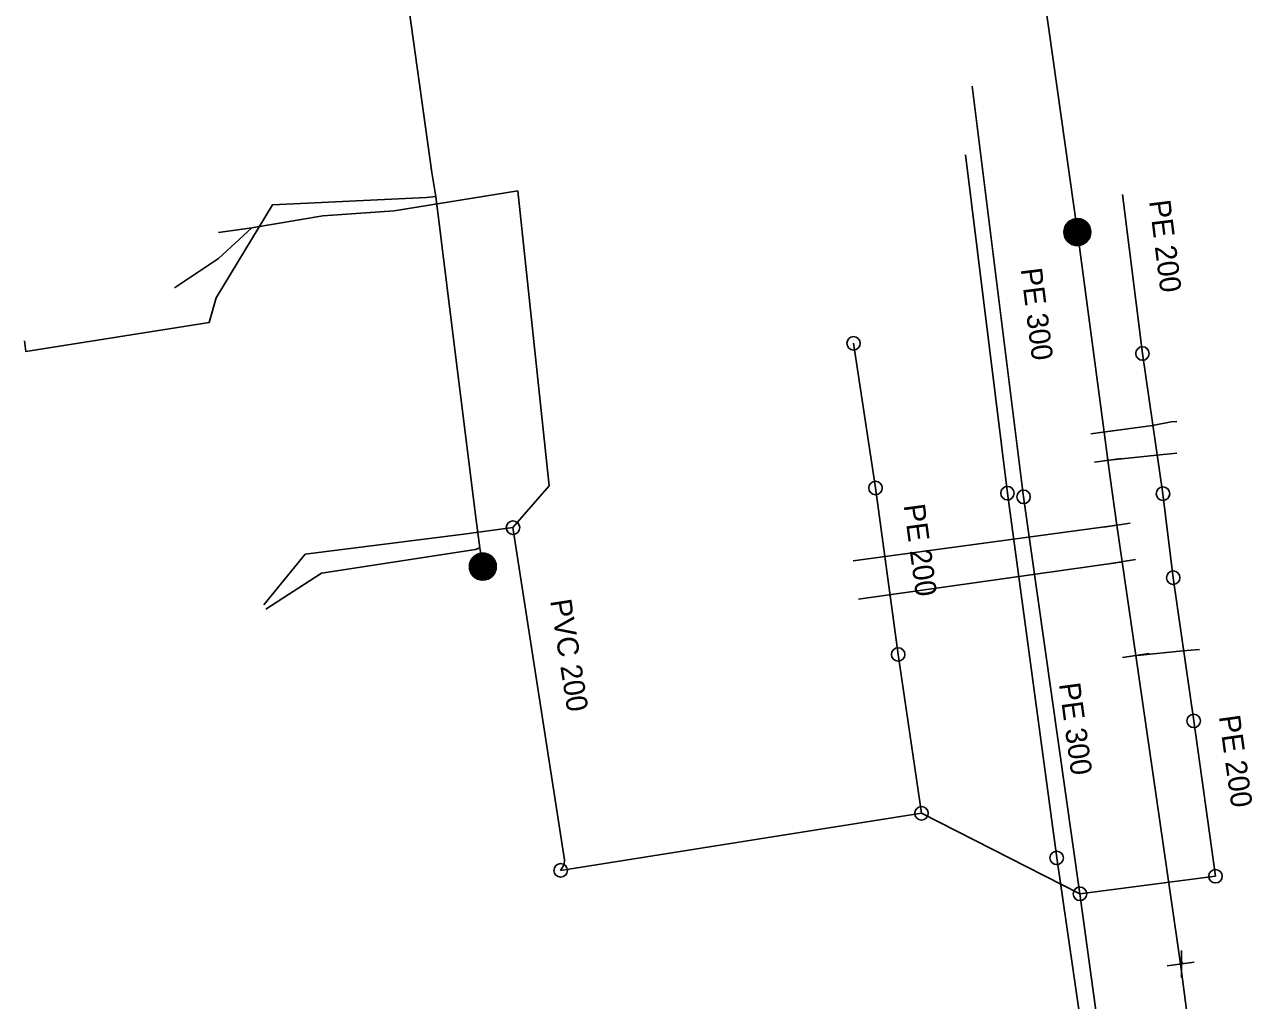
# Model space of a CAD drawing. Extents: x -867696 to -865033, y -1042522 to -1039817.
# Drawn here: x -866756.7 to -866641, y -1040051.9 to -1039959.9 of the extents above; entities that cross this region are included whole.
import ezdxf

# ---------------------------------------------------------------- set-up
doc = ezdxf.new("R2010")
doc.units = 0
for name, color, linetype in [('KN - destova', 7, 'Continuous'), ('KN - jednotna', 7, 'Continuous'), ('KN - popis material', 7, 'Continuous'), ('KN - pripojka', 7, 'Continuous'), ('KN - sachta komora', 7, 'Continuous'), ('KN - splaskova', 7, 'Continuous'), ('Level 1', 7, 'Continuous'), ('V - armatura', 7, 'Continuous'), ('V - hydrant', 7, 'Continuous'), ('V - ostatni', 7, 'Continuous'), ('V - pripojka', 7, 'Continuous'), ('V - rozvadeci', 7, 'Continuous')]:
    doc.layers.add(name, color=color, linetype=linetype)

# ---------------------------------------------------------------- blocks, each defined once
blk = doc.blocks.new('100.M')
at = {"layer": 'Level 1'}
blk.add_circle((0, 0), 1.27, dxfattribs=at)
blk = doc.blocks.new('160')
at = {"layer": 'Level 1'}
for p, q in [((-1.26, -0.04), (0.05, 1.27)), ((-1.26, -0.06), (0.06, 1.27)), ((-1.26, -0.07), (0.08, 1.27)), ((-1.26, -0.09), (0.09, 1.27)), ((-1.26, 0.11), (-0.12, 1.26)), ((-1.26, 0.1), (-0.1, 1.26)), ((-1.26, 0.08), (-0.09, 1.26)), ((-1.26, 0.07), (-0.07, 1.26)), ((-1.26, 0.06), (-0.06, 1.26)), ((-1.26, 0.04), (-0.04, 1.26)), ((-1.26, 0.03), (-0.03, 1.26)), ((-1.26, 0.01), (-0.01, 1.26)), ((-1.26, 0), (0, 1.26)), ((-1.26, -0.02), (0.02, 1.26)), ((-1.26, -0.03), (0.03, 1.26)), ((-1.26, -0.1), (0.1, 1.26)), ((-1.26, -0.11), (0.12, 1.26)), ((-1.26, -0.13), (0.13, 1.26)), ((-1.26, -0.14), (0.14, 1.26)), ((-1.26, 0.17), (-0.18, 1.25)), ((-1.26, 0.15), (-0.16, 1.25)), ((-1.26, 0.14), (-0.15, 1.25)), ((-1.26, 0.13), (-0.13, 1.25)), ((-1.26, -0.16), (0.15, 1.25)), ((-1.26, -0.17), (0.16, 1.25)), ((-1.25, 0.21), (-0.21, 1.25)), ((-1.25, 0.19), (-0.19, 1.25)), ((-1.25, -0.18), (0.17, 1.25)), ((-1.25, -0.19), (0.19, 1.25)), ((-1.25, -0.2), (0.2, 1.24)), ((-1.25, -0.21), (0.21, 1.24)), ((-1.24, 0.25), (-0.24, 1.25)), ((-1.24, 0.23), (-0.22, 1.25)), ((-1.24, -0.22), (0.22, 1.24)), ((-1.24, -0.24), (0.23, 1.24)), ((-1.24, -0.25), (0.25, 1.24)), ((-1.23, 0.27), (-0.26, 1.24)), ((-1.23, 0.29), (-0.28, 1.23)), ((-1.23, -0.26), (0.26, 1.23)), ((-1.23, -0.27), (0.27, 1.23)), ((-1.23, -0.28), (0.28, 1.23)), ((-1.23, -0.29), (0.29, 1.23)), ((-1.22, 0.3), (-0.3, 1.23)), ((-1.22, 0.32), (-0.32, 1.22)), ((-1.22, -0.3), (0.31, 1.22)), ((-1.22, -0.32), (0.32, 1.22)), ((-1.22, -0.33), (0.33, 1.22)), ((-1.21, -0.34), (0.34, 1.22)), ((-1.21, -0.35), (0.35, 1.22)), ((-1.21, 0.36), (-0.36, 1.21)), ((-1.21, 0.34), (-0.34, 1.21)), ((-1.21, -0.36), (0.36, 1.21)), ((-1.21, -0.37), (0.38, 1.21)), ((-1.2, -0.38), (0.39, 1.21)), ((-1.2, 0.38), (-0.38, 1.2)), ((-1.2, -0.39), (0.4, 1.2)), ((-1.2, -0.41), (0.41, 1.2)), ((-1.2, 0.4), (-0.4, 1.19)), ((-1.19, -0.42), (0.42, 1.2)), ((-1.19, 0.42), (-0.43, 1.19)), ((-1.19, -0.43), (0.43, 1.19)), ((-1.19, -0.44), (0.44, 1.19)), ((-1.19, 0.44), (-0.45, 1.18)), ((-1.19, -0.45), (0.45, 1.18)), ((-1.18, -0.46), (0.46, 1.18)), ((-1.18, 0.46), (-0.47, 1.17)), ((-1.18, -0.47), (0.47, 1.17)), ((-1.17, 0.48), (-0.49, 1.17)), ((-1.17, -0.48), (0.48, 1.17)), ((-1.17, -0.49), (0.49, 1.16)), ((-1.16, 0.51), (-0.51, 1.16)), ((-1.16, -0.5), (0.5, 1.16)), ((-1.16, -0.51), (0.5, 1.16)), ((-1.15, -0.52), (0.51, 1.15)), ((-1.15, -0.53), (0.52, 1.15)), ((-1.14, 0.54), (-0.53, 1.15)), ((-1.14, -0.54), (0.53, 1.14)), ((-1.14, -0.54), (0.54, 1.14)), ((-1.13, -0.55), (0.55, 1.13)), ((-1.13, -0.56), (0.56, 1.13)), ((-1.12, 0.58), (-0.56, 1.14)), ((-1.12, -0.57), (0.57, 1.12)), ((-1.12, -0.58), (0.58, 1.12)), ((-1.11, -0.59), (0.59, 1.11)), ((-1.11, -0.6), (0.6, 1.11)), ((-1.1, 0.61), (-0.6, 1.11)), ((-1.1, -0.61), (0.61, 1.11)), ((-1.1, -0.62), (0.62, 1.1)), ((-1.09, -0.63), (0.63, 1.1)), ((-1.09, 0.64), (-0.64, 1.09)), ((-1.09, -0.64), (0.64, 1.09)), ((-1.08, -0.65), (0.65, 1.09)), ((-1.08, -0.65), (0.66, 1.08)), ((-1.07, -0.66), (0.67, 1.08)), ((-1.07, -0.67), (0.68, 1.07)), ((-1.07, 0.67), (-0.68, 1.06)), ((-1.06, -0.68), (0.69, 1.07)), ((-1.06, -0.69), (0.69, 1.06)), ((-1.05, -0.7), (0.7, 1.05)), ((-1.05, -0.71), (0.71, 1.05)), ((-1.05, 0.7), (-0.71, 1.04)), ((-1.04, -0.72), (0.72, 1.04)), ((-1.04, -0.73), (0.72, 1.04)), ((-1.03, -0.74), (0.73, 1.03)), ((-1.03, -0.75), (0.74, 1.02)), ((-1.03, 0.73), (-0.75, 1.01)), ((-1.02, -0.75), (0.75, 1.02)), ((-1.01, -0.76), (0.76, 1.01)), ((-1.01, -0.77), (0.76, 1)), ((-1, -0.77), (0.77, 1)), ((-0.99, -0.78), (0.78, 0.99)), ((-0.99, -0.79), (0.79, 0.98)), ((-0.98, -0.8), (0.79, 0.98)), ((-0.97, -0.8), (0.8, 0.97)), ((-0.97, -0.81), (0.81, 0.97)), ((-0.96, -0.82), (0.82, 0.96)), ((-0.95, -0.83), (0.83, 0.95)), ((-0.95, -0.83), (0.83, 0.95)), ((-0.94, -0.84), (0.84, 0.94)), ((-0.93, -0.85), (0.85, 0.93)), ((-0.93, -0.86), (0.86, 0.93)), ((-0.92, -0.86), (0.86, 0.92)), ((-0.91, 0.87), (-0.79, 0.99)), ((-0.91, -0.87), (0.87, 0.91)), ((-0.91, -0.88), (0.88, 0.91)), ((-0.9, -0.88), (0.89, 0.9)), ((-0.89, -0.89), (0.89, 0.89)), ((-0.88, -0.9), (0.9, 0.89)), ((-0.88, -0.91), (0.91, 0.88)), ((-0.87, -0.91), (0.92, 0.88)), ((-0.86, -0.92), (0.93, 0.87)), ((-0.86, -0.93), (0.93, 0.86)), ((-0.85, -0.94), (0.94, 0.85)), ((-0.84, -0.94), (0.94, 0.84)), ((-0.84, -0.95), (0.95, 0.84)), ((-0.83, -0.96), (0.96, 0.83)), ((-0.82, -0.96), (0.96, 0.82)), ((-0.82, -0.97), (0.97, 0.81)), ((-0.81, -0.98), (0.97, 0.8)), ((-0.8, -0.98), (0.98, 0.8)), ((-0.79, -0.99), (0.99, 0.79)), ((-0.78, -1), (0.99, 0.78)), ((-0.77, -1), (1, 0.77)), ((-0.77, -1.01), (1, 0.76)), ((-0.76, -1.01), (1.01, 0.75)), ((-0.75, -1.02), (1.02, 0.75)), ((-0.74, -1.02), (1.02, 0.74)), ((-0.73, -1.03), (1.03, 0.73)), ((-0.72, -1.03), (1.03, 0.72)), ((-0.71, -1.04), (1.04, 0.71)), ((-0.71, -1.04), (1.04, 0.71)), ((-0.7, -1.05), (1.05, 0.7)), ((-0.69, -1.06), (1.06, 0.69)), ((-0.68, -1.06), (1.06, 0.68)), ((-0.67, -1.07), (1.07, 0.67)), ((-0.66, -1.07), (1.07, 0.66)), ((-0.65, -1.08), (1.08, 0.66)), ((-0.64, -1.08), (1.09, 0.65)), ((-0.64, -1.09), (1.09, 0.64)), ((-0.63, -1.09), (1.1, 0.63)), ((-0.62, -1.1), (1.1, 0.62)), ((-0.61, -1.11), (1.11, 0.62)), ((-0.6, -1.11), (1.12, 0.61)), ((-0.59, -1.12), (1.12, 0.6)), ((-0.58, -1.12), (1.12, 0.59)), ((-0.58, -1.13), (1.13, 0.58)), ((-0.57, -1.13), (1.13, 0.57)), ((-0.56, -1.14), (1.14, 0.56)), ((-0.55, -1.14), (1.14, 0.55)), ((-0.54, -1.15), (1.14, 0.54)), ((-0.53, -1.15), (1.15, 0.52)), ((-0.52, -1.16), (1.15, 0.51)), ((-0.51, -1.16), (1.16, 0.5)), ((-0.5, -1.16), (1.16, 0.49)), ((-0.49, -1.17), (1.16, 0.48)), ((-0.48, -1.17), (1.17, 0.47)), ((-0.47, -1.17), (1.17, 0.46)), ((-0.46, -1.18), (1.18, 0.45)), ((-0.44, -1.18), (1.18, 0.44)), ((-0.43, -1.18), (1.18, 0.43)), ((-0.42, -1.19), (1.19, 0.42)), ((-0.41, -1.19), (1.19, 0.41)), ((-0.4, -1.19), (1.2, 0.4)), ((-0.39, -1.2), (1.2, 0.39)), ((-0.38, -1.2), (1.2, 0.38)), ((-0.37, -1.2), (1.21, 0.37)), ((-0.36, -1.21), (1.21, 0.36)), ((-0.35, -1.21), (1.22, 0.35)), ((-0.34, -1.22), (1.22, 0.34)), ((-0.33, -1.22), (1.22, 0.33)), ((-0.32, -1.22), (1.23, 0.32)), ((-0.31, -1.23), (1.23, 0.31)), ((-0.3, -1.23), (1.23, 0.3)), ((-0.28, -1.23), (1.23, 0.29)), ((-0.27, -1.24), (1.24, 0.27)), ((-0.26, -1.24), (1.24, 0.26)), ((-0.25, -1.24), (1.24, 0.25)), ((-0.24, -1.25), (1.24, 0.24)), ((-0.23, -1.25), (1.24, 0.22)), ((-0.22, -1.25), (1.24, 0.21)), ((-0.2, -1.25), (1.24, 0.2)), ((-0.19, -1.25), (1.25, 0.19)), ((-0.18, -1.25), (1.25, 0.17)), ((-0.16, -1.25), (1.25, 0.16)), ((-0.15, -1.25), (1.25, 0.15)), ((-0.14, -1.25), (1.25, 0.14)), ((-0.12, -1.25), (1.25, 0.12)), ((-0.11, -1.26), (1.26, 0.11)), ((-0.1, -1.26), (1.26, 0.1)), ((-0.08, -1.26), (1.26, 0.09)), ((-0.07, -1.26), (1.26, 0.07)), ((-0.06, -1.26), (1.26, 0.06)), ((-0.04, -1.26), (1.26, 0.05)), ((-0.03, -1.26), (1.27, 0.04)), ((-0.02, -1.26), (1.27, 0.02)), ((0, -1.26), (1.27, 0.01)), ((0.01, -1.26), (1.27, 0)), ((0.02, -1.26), (1.27, -0.02)), ((0.04, -1.27), (1.27, -0.04)), ((0.05, -1.27), (1.26, -0.05)), ((0.06, -1.27), (1.26, -0.07)), ((0.08, -1.27), (1.26, -0.08)), ((0.09, -1.26), (1.26, -0.1)), ((0.11, -1.26), (1.26, -0.12)), ((0.13, -1.26), (1.25, -0.13)), ((0.15, -1.25), (1.25, -0.15)), ((0.16, -1.25), (1.25, -0.17)), ((0.18, -1.25), (1.25, -0.18)), ((0.2, -1.24), (1.24, -0.2)), ((0.22, -1.24), (1.24, -0.21)), ((0.23, -1.24), (1.24, -0.23)), ((0.25, -1.24), (1.24, -0.25)), ((0.27, -1.23), (1.24, -0.26)), ((0.28, -1.23), (1.23, -0.28)), ((0.3, -1.23), (1.23, -0.3)), ((0.32, -1.22), (1.23, -0.31)), ((0.34, -1.22), (1.22, -0.33)), ((0.35, -1.22), (1.22, -0.35)), ((0.37, -1.21), (1.21, -0.38)), ((0.39, -1.21), (1.2, -0.4)), ((0.42, -1.2), (1.19, -0.43)), ((0.44, -1.18), (1.18, -0.45)), ((0.47, -1.17), (1.17, -0.47)), ((0.5, -1.16), (1.16, -0.5)), ((0.52, -1.15), (1.15, -0.52)), ((0.55, -1.13), (1.14, -0.54)), ((0.58, -1.12), (1.13, -0.57)), ((0.6, -1.11), (1.12, -0.59)), ((0.63, -1.1), (1.11, -0.61)), ((0.65, -1.09), (1.08, -0.66)), ((0.69, -1.06), (1.04, -0.72)), ((0.77, -1), (1, -0.77)), ((0.85, -0.93), (0.96, -0.82))]:
    blk.add_line(p, q, dxfattribs=at)
blk.add_circle((0, 0), 1.27, dxfattribs=at)
blk = doc.blocks.new('147')
at = {"layer": 'Level 1'}
blk.add_line((0, 1.27), (0, -1.27), dxfattribs=at)
blk = doc.blocks.new('150')
at = {"layer": 'Level 1'}
blk.add_line((0, 1.27), (0, -1.27), dxfattribs=at)

msp = doc.modelspace()

# ---------------------------------------------------------------- linework, layer by layer
at = {"layer": 'KN - destova'}
for points in [[(-866668.06, -1039972.2), (-866664.1, -1040004.07)], [(-866664.1, -1040004.07), (-866659.46, -1040038.44)], [(-866659.46, -1040038.44), (-866656.16, -1040061.19)]]:
    msp.add_lwpolyline(points, dxfattribs=at)
at = {"layer": 'KN - jednotna'}
for points in [[(-866706.2, -1040039.62), (-866705.86, -1040039.07), (-866705.832, -1040038.62), (-866710.69, -1040007.32)], [(-866706.2, -1040039.62), (-866672.2, -1040034.24)]]:
    msp.add_lwpolyline(points, dxfattribs=at)
at = {"layer": 'KN - pripojka'}
for points in [[(-866710.69, -1040007.32), (-866707.29, -1040003.39), (-866710.24, -1039975.59), (-866721.88, -1039977.48), (-866728.62, -1039977.94), (-866735.3, -1039979.08)], [(-866735.3, -1039979.08), (-866738.448, -1039981.961), (-866742.57, -1039984.72)], [(-866735.3, -1039979.08), (-866738.448, -1039979.521)], [(-866710.69, -1040007.32), (-866715.32, -1040007.93), (-866730.26, -1040009.81), (-866734.17, -1040014.6)]]:
    msp.add_lwpolyline(points, dxfattribs=at)
at = {"layer": 'KN - splaskova'}
for points in [[(-866667.43, -1039965.73), (-866662.58, -1040004.42)], [(-866653.25, -1039975.92), (-866651.38, -1039990.91)], [(-866678.6, -1039989.95), (-866676.53, -1040003.58)], [(-866651.38, -1039990.91), (-866649.45, -1040004.12)], [(-866676.53, -1040003.58), (-866674.4, -1040019.27)], [(-866649.45, -1040004.12), (-866648.48, -1040012.04)], [(-866662.58, -1040004.42), (-866657.27, -1040041.83)], [(-866648.48, -1040012.04), (-866646.55, -1040025.53)], [(-866674.4, -1040019.27), (-866672.2, -1040034.24)], [(-866646.55, -1040025.53), (-866644.5, -1040040.17)], [(-866672.2, -1040034.24), (-866657.27, -1040041.83)], [(-866644.5, -1040040.17), (-866657.27, -1040041.83)], [(-866657.27, -1040041.83), (-866650.99, -1040087.61)]]:
    msp.add_lwpolyline(points, dxfattribs=at)
at = {"layer": 'V - pripojka'}
for points in [[(-866717.962, -1039976.129), (-866718.85, -1039976.21), (-866733.36, -1039976.89), (-866738.65, -1039985.67), (-866739.32, -1039988), (-866756.6, -1039990.72), (-866756.71, -1039989.73)], [(-866655, -1039998.31), (-866654.857, -1039998.294), (-866650.42, -1039997.69), (-866648.67, -1039997.36), (-866648.14, -1039997.32)], [(-866654.64, -1040000.97), (-866654.501, -1040000.963), (-866650.05, -1040000.48), (-866648.15, -1040000.31)], [(-866653.78, -1040007.09), (-866654.023, -1040007.125), (-866678.64, -1040010.45)], [(-866713.81, -1040009.22), (-866714.23, -1040009.37), (-866728.72, -1040011.6), (-866733.97, -1040015.01)], [(-866713.53, -1040010.99), (-866713.454, -1040011.627)], [(-866653.28, -1040010.53), (-866653.461, -1040010.567), (-866678.15, -1040014.06)], [(-866652, -1040019.37), (-866651.887, -1040019.359), (-866647.56, -1040018.93), (-866646.02, -1040018.81)], [(-866647.78, -1040048.43), (-866647.69, -1040048.43), (-866647.53, -1040048.29)]]:
    msp.add_lwpolyline(points, dxfattribs=at)
at = {"layer": 'V - rozvadeci'}
for points in [[(-866738.62, -1039816.98), (-866737.33, -1039833.04), (-866733.14, -1039860.86), (-866731.06, -1039875.66), (-866728.55, -1039894.98), (-866725.88, -1039914.58), (-866723.57, -1039934.47), (-866721.07, -1039954.26), (-866718.33, -1039973.86), (-866717.962, -1039976.129), (-866715.87, -1039993.09), (-866714.15, -1040006.6), (-866713.81, -1040009.22)], [(-866662.53, -1039943.87), (-866657.51, -1039979.47)], [(-866657.51, -1039979.47), (-866655, -1039998.31)], [(-866655, -1039998.31), (-866654.64, -1040000.97)], [(-866654.64, -1040000.97), (-866654.43, -1040002.58), (-866653.78, -1040007.09)], [(-866653.78, -1040007.09), (-866653.28, -1040010.53)], [(-866713.81, -1040009.22), (-866713.53, -1040010.99)], [(-866653.28, -1040010.53), (-866652, -1040019.37)], [(-866652, -1040019.37), (-866647.78, -1040048.43)], [(-866647.78, -1040048.43), (-866645.5, -1040066.02), (-866642.35, -1040088.21)]]:
    msp.add_lwpolyline(points, dxfattribs=at)

# ---------------------------------------------------------------- block references
at = {"layer": 'KN - sachta komora'}
for p, xscale, yscale, rotation in [((-866678.6, -1039989.95), 0.5000000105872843, 0.5000000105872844, -81.00000039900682), ((-866651.38, -1039990.91), 0.49999999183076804, 0.49999999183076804, 98.00000038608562), ((-866676.53, -1040003.58), 0.5000000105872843, 0.5000000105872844, 98.99999960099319), ((-866664.1, -1040004.07), 0.49999999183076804, 0.49999999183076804, 98.00000038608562), ((-866662.58, -1040004.42), 0.49999999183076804, 0.49999999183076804, 98.00000038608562), ((-866649.45, -1040004.12), 0.49999999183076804, 0.49999999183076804, 98.00000038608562), ((-866710.69, -1040007.32), 0.5000000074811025, 0.5000000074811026, 89.0000000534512), ((-866648.48, -1040012.04), 0.49999999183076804, 0.49999999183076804, 98.00000038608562), ((-866674.4, -1040019.27), 0.5000000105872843, 0.5000000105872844, 98.99999960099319), ((-866646.55, -1040025.53), 0.5000000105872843, 0.5000000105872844, 98.99999960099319), ((-866672.2, -1040034.24), 0.5000000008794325, 0.5000000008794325, 125.99999933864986), ((-866659.46, -1040038.44), 0.49999999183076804, 0.49999999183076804, 98.00000038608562), ((-866706.2, -1040039.62), 0.4999999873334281, 0.499999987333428, 124.00000045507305), ((-866644.5, -1040040.17), 0.49999999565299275, 0.4999999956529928, -127.00000193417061), ((-866657.27, -1040041.83), 0.5041888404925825, 0.5041888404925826, 168.37362119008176)]:
    msp.add_blockref('100.M', p, dxfattribs=dict(at, xscale=xscale, yscale=yscale, rotation=rotation))
at = {"layer": 'V - armatura'}
for p, xscale, yscale, rotation in [((-866655, -1039998.31), 0.9999999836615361, 0.9999999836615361, 98.00000038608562), ((-866654.64, -1040000.97), 0.9999999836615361, 0.9999999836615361, 98.00000038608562), ((-866653.78, -1040007.09), 1.0000000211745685, 1.0000000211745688, 98.99999960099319), ((-866653.28, -1040010.53), 1.0000000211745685, 1.0000000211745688, 98.99999960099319), ((-866652, -1040019.37), 1.0000000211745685, 1.0000000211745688, 98.99999960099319), ((-866647.78, -1040048.43), 0.9999999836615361, 0.9999999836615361, 98.00000038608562)]:
    msp.add_blockref('147', p, dxfattribs=dict(at, xscale=xscale, yscale=yscale, rotation=rotation))
at = {"layer": 'V - hydrant'}
msp.add_blockref('150', (-866647.69, -1040048.43), dxfattribs=at)
at = {"layer": 'V - ostatni'}
for p, xscale, yscale, rotation in [((-866657.51, -1039979.47), 0.9999999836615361, 0.9999999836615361, 98.00000038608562), ((-866713.53, -1040010.99), 1.0000000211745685, 1.0000000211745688, -81.00000039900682)]:
    msp.add_blockref('160', p, dxfattribs=dict(at, xscale=xscale, yscale=yscale, rotation=rotation))

# ---------------------------------------------------------------- texts
at = {"layer": 'KN - popis material'}
for s, rotation, p in [('PE 200', 277.11, (-866650.752, -1039976.549)), ('PE 300', 277.15, (-866662.853, -1039982.952)), ('PE 200', 277.73, (-866673.886, -1040005.211)), ('PVC 200', 278.82, (-866707.194, -1040014.199)), ('PE 300', 277.69, (-866659.251, -1040022.05)), ('PE 200', 277.97, (-866644.186, -1040025.109))]:
    msp.add_text(s, height=2, rotation=rotation, dxfattribs=at).set_placement(p)

doc.saveas('drawing.dxf')
